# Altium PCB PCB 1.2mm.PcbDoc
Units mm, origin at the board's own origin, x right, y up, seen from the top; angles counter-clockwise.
Board outline 105 x 74.8 mm, 2 copper layers (Top Layer, Bottom Layer); 5 components, 1 nets, 24 pads, 0 vias.
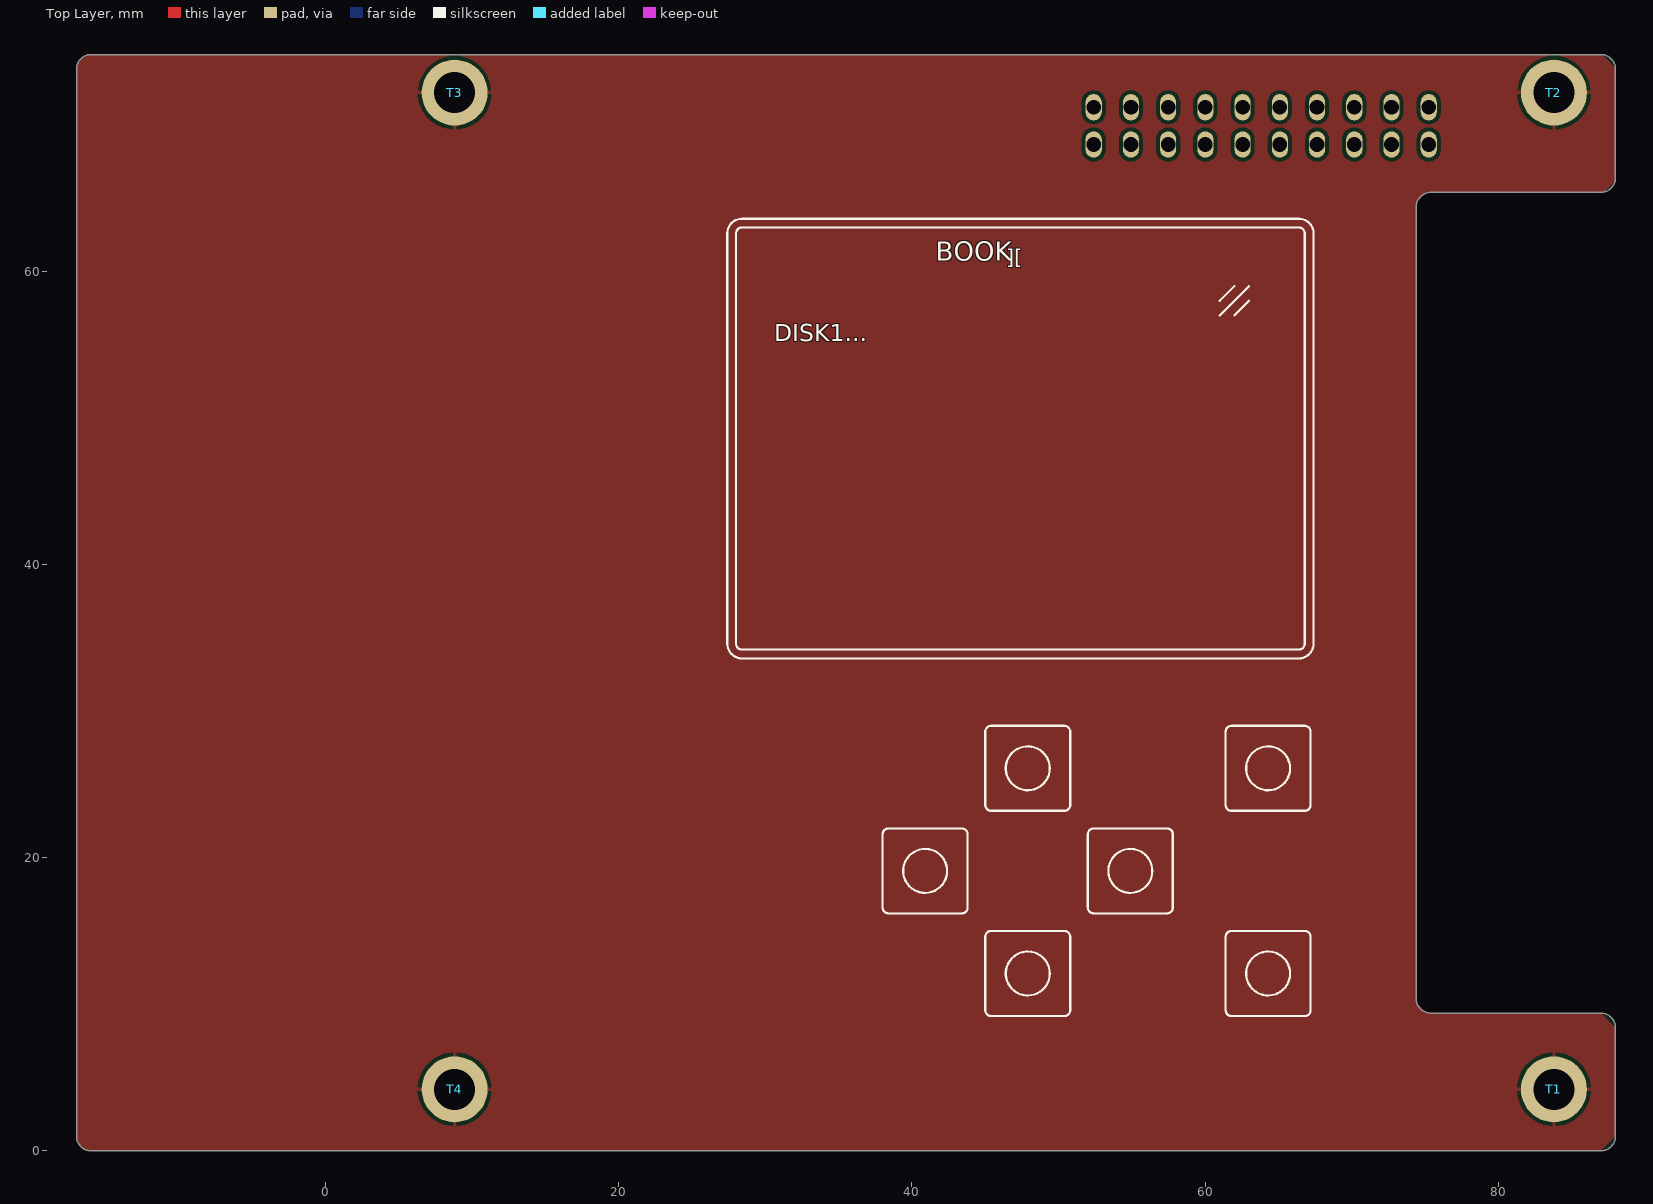
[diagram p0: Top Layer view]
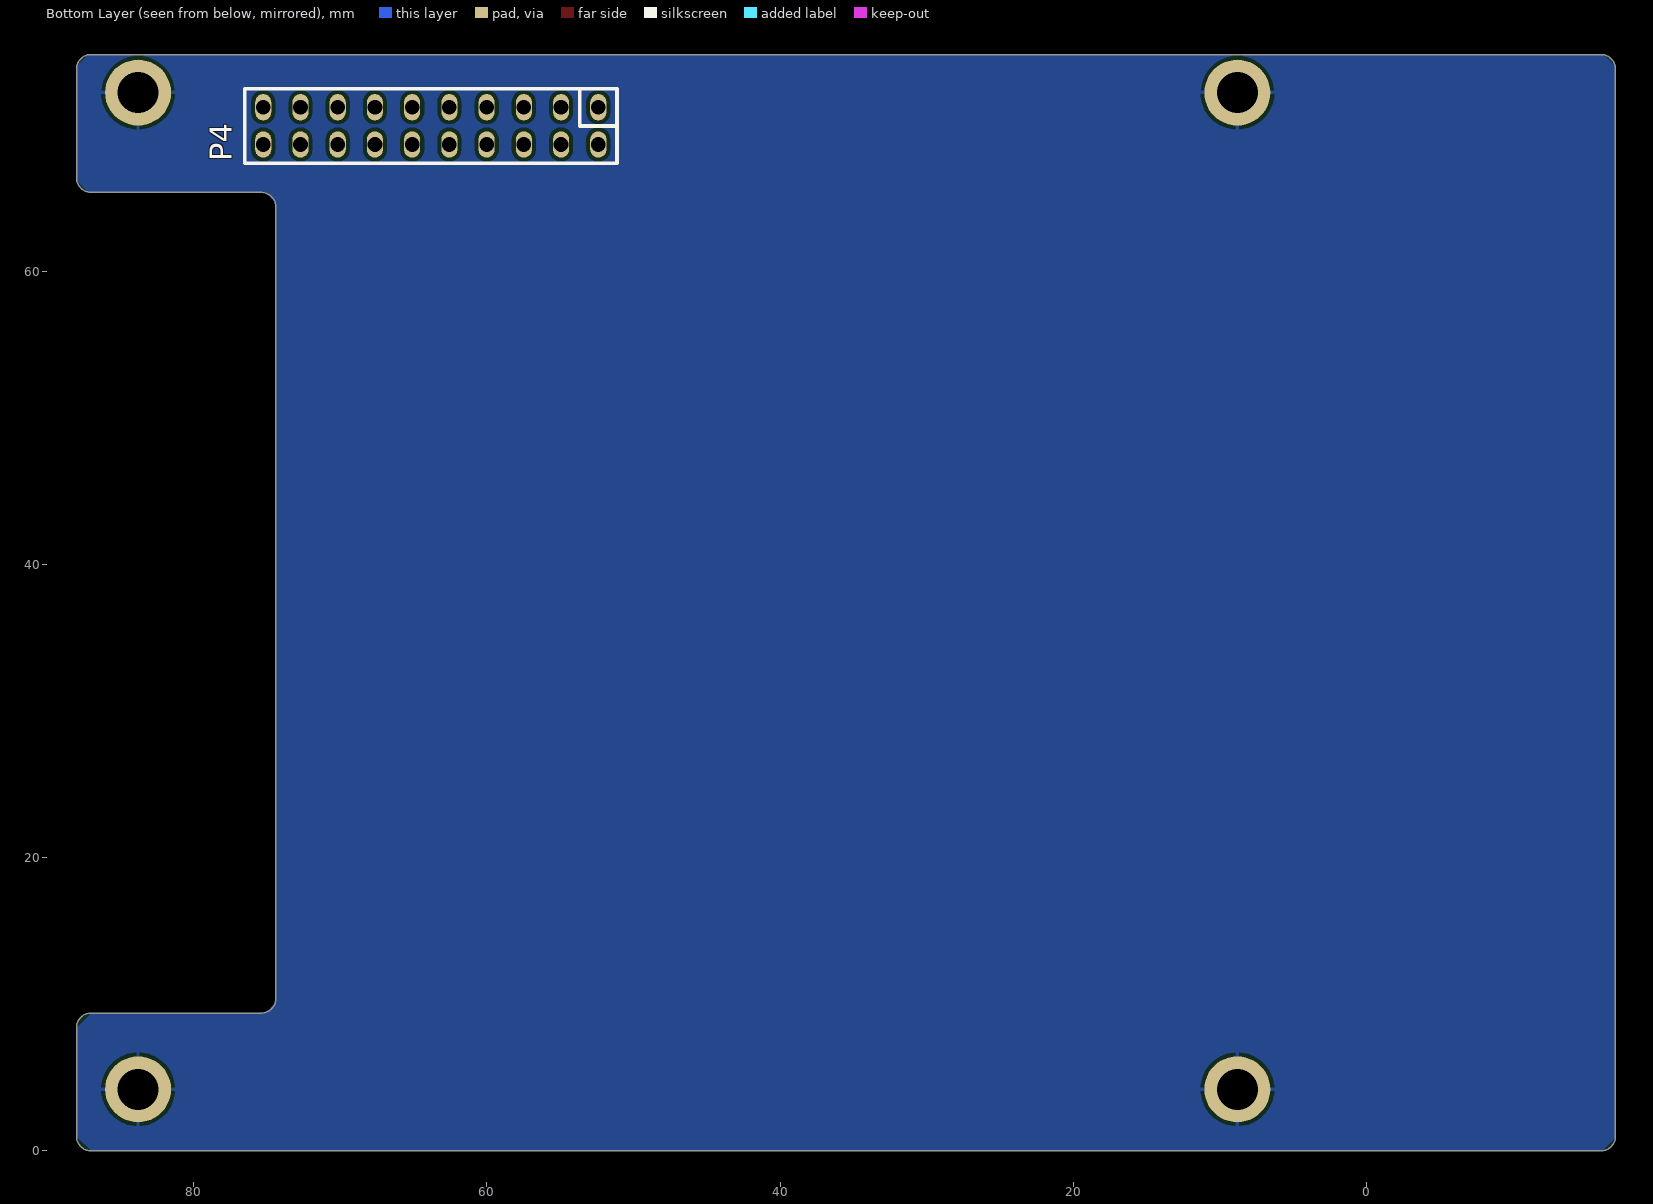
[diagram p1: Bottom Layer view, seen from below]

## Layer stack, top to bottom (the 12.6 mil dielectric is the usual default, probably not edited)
Top Solder: solder mask 0.0102, Solder Resist, Dk 3.5
Top Layer: signal copper 0.0356
Dielectric1: dielectric 0.32, FR-4, Dk 4.8
Bottom Layer: signal copper 0.0356
Bottom Solder: solder mask 0.0102, Solder Resist, Dk 3.5

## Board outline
-17,1 ccw(c-16,1) -16,0 87,0 ccw(c87,1) 88,1 88,8.4 ccw(c87,8.4) 87,9.4 75.4,9.4 cw(c75.4,10.4) 74.4,10.4 74.4,64.4 cw(c75.4,64.4) 75.4,65.4 87,65.4 ccw(c87,66.4) 88,66.4 88,73.8 ccw(c87,73.8) 87,74.8 -16,74.8 ccw(c-16,73.8) -17,73.8

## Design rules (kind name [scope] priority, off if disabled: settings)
Clearance Clearance_1 [InNet('VCC')  or InNet('+12V') or InNet('-12V')] p1: gap=0.178 ignorepadtopadclearanceinfootprint=FALSE except(0: Arc-Hole Track-Hole SMDPad-Hole THPad-Hole Via-Hole Fill-Hole Poly-Hole Region-Hole Text-Hole; 0.381: Arc-Fill Arc-Poly Arc-Region Track-Fill Track-Poly Track-Region SMDPad-Fill SMDPad-Poly SMDPad-Region THPad-Fill THPad-Poly THPad-Region Via-Fill Via-Poly Via-Region Fill-Fill Fill-Poly Fill-Region Poly-Poly Poly-Region Region-Region)
Clearance [All] p2: gap=0.178 ignorepadtopadclearanceinfootprint=FALSE except(0: Arc-Hole Track-Hole SMDPad-Hole THPad-Hole Via-Hole Fill-Hole Poly-Hole Region-Hole Text-Hole; 0.254: Arc-Fill Arc-Poly Arc-Region Track-Fill Track-Poly Track-Region SMDPad-Fill SMDPad-Poly SMDPad-Region THPad-Fill THPad-Poly THPad-Region Via-Fill Via-Poly Via-Region Fill-Fill Fill-Poly Fill-Region Poly-Poly Poly-Region Region-Region)
ComponentClearance [All] p1: gap=0 collisioncheckmode=3 verticalgap=0 showdistances=FALSE
HoleSize [All] p1: absolutevalues=TRUE maxlimit=25.4 minlimit=0.025 maxpercent=80.000 minpercent=20.000
HoleToHoleClearance [All] p1: gap=0 allowstackedmicrovias=TRUE
MinimumSolderMaskSliver [All] p1: minsoldermaskwidth=0
PlaneClearance [All] p1: clearance=0
PolygonConnect PolygonConnect_1 [InNet('GND')] p1: thpad.connectstyle=Relief thpad.reliefconductorwidth=0.254 thpad.reliefentries=4 thpad.polygonreliefangle="90 Angle" thpad.airgapwidth=0.254 smdpad.connectstyle=Relief smdpad.reliefconductorwidth=0.254 smdpad.reliefentries=4 smdpad.polygonreliefangle="90 Angle" smdpad.airgapwidth=0.254 via.connectstyle=Direct via.reliefconductorwidth=0.254 via.reliefentries=4 via.polygonreliefangle="90 Angle" via.airgapwidth=0.254
PolygonConnect [All] p2: connectstyle=Relief reliefconductorwidth=0.254 reliefentries=4 polygonreliefangle="90 Angle" airgapwidth=0.254
RoutingVias [All] p1: holewidth=0.356 width=0.686 viastyle="Through Hole" minholewidth=0.254 minwidth=0.508 maxholewidth=1.27 maxwidth=2.54
SilkToSilkClearance [All] p1: silktosilkclearance=0
SilkToSolderMaskClearance [IsPad] p1: minsilkscreentomaskgap=0 clearancetoexposedcopper=TRUE
SolderMaskExpansion [All] p1: expansion=0.102 istentingtop=FALSE
Width [All] p1: maxlimit=7.62 minlimit=0.152 preferedwidth=0.178 minimp=50.000000 maximp=50.000000 favimp=50.000000
23 further rules are at their usual default settings.

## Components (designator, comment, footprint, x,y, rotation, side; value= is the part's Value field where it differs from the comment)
P4 "CON2x10" XH-2x10 52.4,71.2 r0 bottom
T1 "CON1" M2.8D4.5 83.8,4.2 r0 top
T2 "CON1" M2.8D4.5 83.8,72.2 r0 top
T3 "CON1" M2.8D4.5 8.8,72.2 r0 top
T4 "CON1" M2.8D4.5 8.8,4.2 r0 top

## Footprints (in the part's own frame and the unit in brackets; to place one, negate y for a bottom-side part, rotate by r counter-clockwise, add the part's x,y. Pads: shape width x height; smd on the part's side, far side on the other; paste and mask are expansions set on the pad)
M2.8D4.5 [mm]
  round 4.5 hole 2.8: 1(0,0)
XH-2x10 [mm]
  oval 1.1x1.8 hole 1: 1(0,0) 2(0,2.54) 3(2.54,0) 4(2.54,2.54) 5(5.08,0) 6(5.08,2.54) 7(7.62,0) 8(7.62,2.54) 9(10.16,0) 10(10.16,2.54) 11(12.7,0) 12(12.7,2.54) 13(15.24,0) 14(15.24,2.54) 15(17.78,0) 16(17.78,2.54) 17(20.32,0) 18(20.32,2.54) 19(22.86,0) 20(22.86,2.54)
  silkscreen extent -1.27,-1.27 24.13,3.81

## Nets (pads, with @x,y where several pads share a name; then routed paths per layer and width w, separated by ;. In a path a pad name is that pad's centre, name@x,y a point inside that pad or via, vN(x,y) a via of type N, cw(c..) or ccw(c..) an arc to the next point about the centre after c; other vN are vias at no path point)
GND: T1.1 T2.1 T3.1 T4.1
pads on no net: P4.1 P4.2 P4.3 P4.4 P4.5 P4.6 P4.7 P4.8 P4.9 P4.10 P4.11 P4.12 P4.13 P4.14 P4.15 P4.16 P4.17 P4.18 P4.19 P4.20

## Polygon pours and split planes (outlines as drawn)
GND on Top Layer "Top Layer-No Net 1" (solid, remove dead copper, pour order 0): -16.3,74.8 -17,74.1 -17,0.7 -16.3,0 87,0 88,1 88,8.4 87,9.4 75.1,9.4 74.4,10.1 74.4,64.7 75.1,65.4 87.2,65.4 88,66.2 88,73.9 87.1,74.8
GND on Bottom Layer "Top Layer-No Net 1" (solid, remove dead copper, pour order 1): -17,0.9 -16.1,0 87,0 87.9,0.9 87.9,1 88,1 88,8.4 87,9.4 75.1,9.4 74.4,10.1 74.4,64.7 75.1,65.4 87.2,65.4 88,66.2 88,74 87.2,74.8 -16.2,74.8 -17,74

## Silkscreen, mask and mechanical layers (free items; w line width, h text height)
Top Overlay:
  circle w0.15: c64.3,12.1 r1.5
  circle w0.15: c64.3,26.1 r1.5
  circle w0.15: c47.9,12.1 r1.5
  circle w0.15: c40.9,19.1 r1.5
  circle w0.15: c47.9,26.1 r1.5
  circle w0.15: c54.9,19.1 r1.5
  lines w0.15: 61,57 63,59 ; 61,58 62,59 ; 62,57 63,58 ; 62,59 62,59 ; 27.4,34.6 ccw(c28.4,34.6) 28.4,33.6 66.4,33.6 ccw(c66.4,34.6) 67.4,34.6 67.4,62.6 ccw(c66.4,62.6) 66.4,63.6 28.4,63.6 ccw(c28.4,62.6) 27.4,62.6 27.4,34.6 ; 28,34.6 ccw(c28.4,34.6) 28.4,34.2 66.4,34.2 ccw(c66.4,34.6) 66.8,34.6 66.8,62.6 ccw(c66.4,62.6) 66.4,63 28.4,63 ccw(c28.4,62.6) 28,62.6 28,34.6 ; 38,16.6 ccw(c38.4,16.6) 38.4,16.2 43.4,16.2 ccw(c43.4,16.6) 43.8,16.6 43.8,21.6 ccw(c43.4,21.6) 43.4,22 38.4,22 ccw(c38.4,21.6) 38,21.6 38,16.6 ; 45,9.6 ccw(c45.4,9.6) 45.4,9.2 50.4,9.2 ccw(c50.4,9.6) 50.8,9.6 50.8,14.6 ccw(c50.4,14.6) 50.4,15 45.4,15 ccw(c45.4,14.6) 45,14.6 45,9.6 ; 45,23.6 ccw(c45.4,23.6) 45.4,23.2 50.4,23.2 ccw(c50.4,23.6) 50.8,23.6 50.8,28.6 ccw(c50.4,28.6) 50.4,29 45.4,29 ccw(c45.4,28.6) 45,28.6 45,23.6 ; 52,16.6 ccw(c52.4,16.6) 52.4,16.2 57.4,16.2 ccw(c57.4,16.6) 57.8,16.6 57.8,21.6 ccw(c57.4,21.6) 57.4,22 52.4,22 ccw(c52.4,21.6) 52,21.6 52,16.6 ; 61.4,9.6 ccw(c61.8,9.6) 61.8,9.2 66.8,9.2 ccw(c66.8,9.6) 67.2,9.6 67.2,14.6 ccw(c66.8,14.6) 66.8,15 61.8,15 ccw(c61.8,14.6) 61.4,14.6 61.4,9.6 ; 61.4,23.6 ccw(c61.8,23.6) 61.8,23.2 66.8,23.2 ccw(c66.8,23.6) 67.2,23.6 67.2,28.6 ccw(c66.8,28.6) 66.8,29 61.8,29 ccw(c61.8,28.6) 61.4,28.6 61.4,23.6
  text "BOOK" at 41.624,60.27 h2.2
  text "][" at 46.424,60.098 h1.8
  text "DISK1..." at 30.612,54.835 h2
Mechanical 1:
  the board outline again, w0.15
